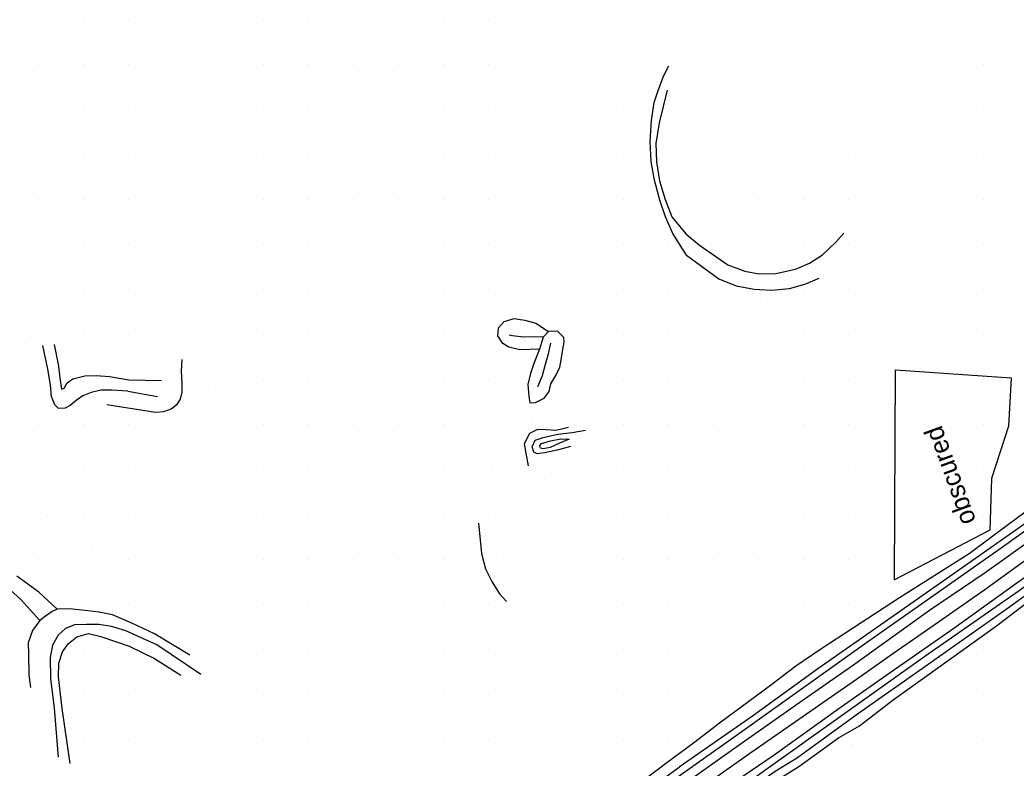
# Model space of a CAD drawing. Extents: x 524772 to 528246, y 273285 to 283088.
# Drawn here: x 526817.7 to 527033.7, y 277669.6 to 277831.8 of the extents above; entities that cross this region are included whole.
import ezdxf

# ---------------------------------------------------------------- set-up
doc = ezdxf.new("R2010")
doc.units = 0
for name, color, linetype in [('Exist DTM Crownline', 7, 'Continuous'), ('Exist Roads EOP', 7, 'Continuous'), ('Old_Level_12', 7, 'Continuous'), ('PH Exist DTM Breakline', 7, 'Continuous'), ('PH Exist DTM Point', 7, 'Continuous')]:
    doc.layers.add(name, color=color, linetype=linetype)

msp = doc.modelspace()

# ---------------------------------------------------------------- linework, layer by layer
at = {"layer": 'Exist DTM Crownline'}
msp.add_lwpolyline([(527093.29, 277754.92), (527081.03, 277746.29), (527067.8, 277736.57), (527053.6, 277726.78), (527037.66, 277716.04), (527026.92, 277708.27), (527016.11, 277700.77), (527006.93, 277694.41), (526999.08, 277688.78), (526989.17, 277681.93), (526976.35, 277673.09), (526967.09, 277666.46), (526959.31, 277660.84), (526949.06, 277653.53), (526940.89, 277647.53)], dxfattribs=at)
at = {"layer": 'Exist Roads EOP'}
for points in [[(526885.22, 277587.83), (526890.27, 277593.98), (526898.57, 277603.91), (526907.81, 277613.97), (526915.57, 277622.11), (526923.58, 277629.48), (526930.09, 277635.08), (526937.2, 277641.12), (526944.39, 277646.71), (526953.26, 277652.95), (526962.28, 277659.19), (526969.67, 277664.58), (526981.23, 277672.5), (526995.03, 277682.41), (527006.12, 277690.17), (527020.16, 277699.94), (527033.86, 277709.75), (527047.72, 277719.55), (527068.03, 277733.58), (527084.83, 277745.52), (527098.58, 277755.38)], [(527073.71, 277745.14), (527062.62, 277737.07), (527050.76, 277728.61), (527038.34, 277720.01), (527026.75, 277711.81), (527014.92, 277703.74), (526998.22, 277691.78), (526986.82, 277683.81), (526973.67, 277674.61), (526958.94, 277664.18), (526946.06, 277655.01), (526936.77, 277648.03), (526928.24, 277641.04), (526919.76, 277633.86), (526914.72, 277629.34), (526908.53, 277623.32), (526902.38, 277616.86), (526896.4, 277610.16), (526890.7, 277603.88), (526884.19, 277596.4), (526873.91, 277582.93)]]:
    msp.add_lwpolyline(points, dxfattribs=at)
at = {"layer": 'Old_Level_12'}
msp.add_lwpolyline([(527007.33, 277710.58), (527007.56, 277755.97), (527032.58, 277754.19), (527032.02, 277743.7), (527028.35, 277732.4), (527027.97, 277721.18), (527007.15, 277710.38)], dxfattribs=at)
at = {"layer": 'PH Exist DTM Breakline'}
for points in [[(526962.21, 277780.83), (526959.27, 277785.49), (526957.64, 277789.13), (526956.43, 277792.7), (526955.25, 277797.02), (526954.57, 277801.08), (526954.32, 277805.45), (526954.62, 277810.02), (526955.24, 277813.86), (526956.04, 277816.29), (526957.23, 277819.62), (526958.39, 277821.82)], [(526958, 277816.59), (526956.29, 277809.48), (526955.55, 277805.01), (526955.68, 277801), (526956.37, 277796.9), (526957.57, 277792.85), (526959.03, 277789.12), (526962.07, 277785.43), (526965.07, 277782.97)], [(526965.07, 277782.97), (526971.16, 277778.71), (526974.9, 277777.31), (526977.96, 277776.74), (526981.61, 277776.83), (526985.85, 277777.78), (526988.88, 277779.05), (526991.71, 277780.89), (526994.56, 277783.58), (526996.34, 277785.59)], [(526962.21, 277780.83), (526969.2, 277775.63), (526972.96, 277774.14), (526976.86, 277773.41), (526980.65, 277773.21), (526984.56, 277773.59), (526987.87, 277774.51), (526990.98, 277775.8)], [(526930.35, 277760.39), (526926.06, 277760.3), (526923.73, 277760.83), (526922.38, 277761.62), (526921.33, 277763.3), (526921.45, 277765.07), (526922.7, 277766.4), (526924.83, 277767.08), (526927.19, 277766.73), (526929.58, 277766.03), (526932.29, 277764.28)], [(526928.22, 277748.82), (526929.52, 277748.83), (526931.33, 277749.79), (526932.42, 277751.25), (526932.81, 277752.89), (526933.87, 277754.68), (526934.78, 277756.54), (526935.07, 277758.11), (526935.31, 277759.99), (526935.73, 277761.93), (526935.64, 277762.97), (526934.24, 277764.29), (526932.29, 277764.28), (526931.15, 277763.04), (526930.35, 277760.39), (526929.12, 277757.29), (526928.39, 277755.17), (526927.81, 277752.76), (526928.02, 277750.23), (526928.22, 277748.82)], [(526931.15, 277763.04), (526929.22, 277763.06), (526926.85, 277763.04), (526924.49, 277763.29), (526923.76, 277763.48)], [(526841.11, 277751.35), (526837.66, 277751.53), (526835.28, 277751.53), (526833.18, 277751.02), (526831.36, 277750.28), (526829.92, 277749.29), (526828.59, 277748.18), (526827.51, 277747.66), (526826.06, 277747.56), (526825.26, 277748.38), (526824.54, 277750.14), (526824.36, 277752.67), (526823.76, 277756.05), (526822.71, 277761.18)], [(526825.14, 277761.46), (526826.05, 277756.72), (526826.36, 277754.24), (526826.75, 277751.73), (526827.28, 277751.96), (526827.93, 277753.1), (526829.17, 277753.98), (526831.81, 277754.64), (526834.27, 277754.71), (526837.15, 277754.5), (526841.32, 277753.76)], [(526929.99, 277752.36), (526931.02, 277754.73), (526931.62, 277757.18), (526932.32, 277759.38), (526932.79, 277761.74)], [(526836.52, 277748.43), (526847.07, 277746.73), (526848.89, 277746.89), (526850.5, 277747.51), (526851.86, 277748.56), (526852.54, 277749.6), (526852.86, 277751.11), (526852.86, 277753), (526852.77, 277755.62), (526852.9, 277758.18)], [(526841.32, 277753.76), (526848.38, 277753.61)], [(527075.52, 277754.93), (527068.44, 277748.79), (527063.35, 277744.94), (527058.17, 277741.29), (527051.67, 277736.65), (527043.67, 277731.01), (527032.04, 277722.43), (527023.53, 277716.09), (527008.38, 277706.51), (526998.17, 277699.85), (526991.36, 277695.39), (526985.93, 277691.7), (526980.41, 277687.52), (526969.4, 277679.37), (526963.99, 277675.24), (526957.69, 277670.53)], [(527079.57, 277754.11), (527075.01, 277750.71), (527070.26, 277747.22), (527065.63, 277743.82), (527060.79, 277740.44), (527056.56, 277737.99), (527053.73, 277735.59), (527045.46, 277729.87), (527038.27, 277724.47), (527022.21, 277713.17), (527003.65, 277700.19), (526990.72, 277691.1), (526976.52, 277680.84), (526960.65, 277669.83)], [(526841.11, 277751.35), (526847.57, 277750.16)], [(526942.58, 277655.06), (526958.38, 277666.35), (526976, 277678.83), (527000.52, 277696.3), (527030.41, 277717.38), (527054.44, 277734.53), (527067, 277743.33), (527080.48, 277752.77)], [(526936.64, 277743.43), (526933.9, 277742.8), (526931.82, 277742.93), (526929.93, 277743.04), (526928.15, 277742.12), (526927.03, 277739.93), (526927.36, 277737.87), (526927.93, 277735.13)], [(526937.04, 277739.33), (526934.45, 277738.57), (526931.41, 277737.95), (526929.86, 277737.71), (526929.14, 277738.11), (526928.76, 277739.26), (526929.41, 277740.69), (526931.17, 277741.26), (526934.33, 277741.97), (526937.45, 277742.37), (526940.29, 277742.84)], [(526936.78, 277740.9), (526934.71, 277740.04), (526932.67, 277739.14), (526931.13, 277738.8), (526930.6, 277738.98), (526930.46, 277739.51), (526930.79, 277739.98), (526932.76, 277740.58), (526934.99, 277740.98), (526936.78, 277740.9)], [(527058.86, 277725.19), (527048.05, 277718.02), (527034.11, 277707.88), (527013.87, 277693.78), (526988.75, 277675.91), (526966.56, 277660.08)], [(526917.15, 277722.71), (526917.75, 277716.1), (526918.62, 277712.82), (526920.05, 277710.08), (526921.68, 277707.36), (526923.17, 277705.69)], [(526967.43, 277659.07), (526981.45, 277668.96), (526986.25, 277671.89), (526999.31, 277681.36), (527011.45, 277689.89), (527031.49, 277704.04), (527043.48, 277712.72), (527057.63, 277722.76)], [(526968.48, 277657.57), (526979.98, 277665.83), (526986.56, 277669.97), (526995.15, 277676.16), (526999.73, 277678.75), (527007.02, 277684.39), (527029.45, 277700.46), (527036.17, 277705.56), (527043.04, 277710.22), (527053.9, 277717.96)], [(526798.27, 277713.39), (526807.25, 277712.33), (526812.14, 277710.59), (526815.66, 277708.2), (526817.9, 277706.15), (526822.02, 277701.62)], [(526825.79, 277704.08), (526821.82, 277707.78), (526817.02, 277711.2)], [(526854.54, 277694.09), (526846.9, 277698.75), (526842, 277701.01), (526837.78, 277702.82), (526834.86, 277703.38), (526832.45, 277703.7), (526828.44, 277704.1), (526825.79, 277704.08), (526824.72, 277703.58), (526823.23, 277702.57), (526822.02, 277701.62), (526820.46, 277699.43), (526819.5, 277696.77), (526819.58, 277694.27), (526819.66, 277689.81), (526820, 277687.1)], [(526856.96, 277689.91), (526847.41, 277696.3), (526840.69, 277699.38), (526837.6, 277700.32), (526834.87, 277700.74), (526832.16, 277700.76), (526829.53, 277700.67), (526827.56, 277699.9), (526825.98, 277698.39), (526824.76, 277696.28), (526824.25, 277693.56), (526824.34, 277689.02), (526825.15, 277682.57), (526826.04, 277671.99)], [(526828.63, 277670.63), (526826.89, 277682.54), (526826.06, 277689.36), (526826.17, 277692.35), (526826.98, 277694.78), (526828.22, 277696.62), (526830.07, 277698.08), (526832.56, 277698.79), (526835.24, 277698.13), (526841.43, 277696.02), (526846.87, 277693.35), (526852.59, 277689.72)], [(526957.69, 277670.53), (526948.03, 277663.24), (526943.52, 277659.92), (526939.57, 277656.8), (526936.9, 277654.7), (526934.42, 277652.53), (526930.44, 277649.43), (526926.91, 277646.85), (526922.77, 277643.7), (526917.51, 277639.25), (526915.3, 277637.35), (526912.49, 277634.7), (526910.31, 277632.45), (526908.73, 277631.24), (526907.63, 277630.54), (526906.22, 277630.82), (526904.48, 277631.8), (526902.72, 277633.12), (526900.72, 277635.16), (526897.24, 277638.62)], [(526906.73, 277627.75), (526910.97, 277630.83), (526917.85, 277636.34), (526926.38, 277643.64), (526931.93, 277648.51), (526935.95, 277651.72), (526940.95, 277655.65), (526944.84, 277658.6), (526948.95, 277661.37), (526955.16, 277665.84), (526960.65, 277669.83)]]:
    msp.add_lwpolyline(points, dxfattribs=at)
at = {"layer": 'PH Exist DTM Point'}
for p, q in [((526821.81, 277831.79), (526821.81, 277831.79)), ((526831.56, 277831.79), (526831.56, 277831.79)), ((526841.32, 277831.79), (526841.32, 277831.79)), ((526851.07, 277831.79), (526851.07, 277831.79)), ((526860.82, 277831.79), (526860.82, 277831.79)), ((526870.58, 277831.79), (526870.58, 277831.79)), ((526880.33, 277831.79), (526880.33, 277831.79)), ((526890.09, 277831.79), (526890.09, 277831.79)), ((526899.84, 277831.79), (526899.84, 277831.79)), ((526909.59, 277831.79), (526909.59, 277831.79)), ((526919.35, 277831.79), (526919.35, 277831.79)), ((526929.1, 277831.79), (526929.1, 277831.79)), ((526938.85, 277831.79), (526938.85, 277831.79)), ((526821.81, 277822.03), (526821.81, 277822.03)), ((526831.56, 277822.03), (526831.56, 277822.03)), ((526841.32, 277822.03), (526841.32, 277822.03)), ((526851.07, 277822.03), (526851.07, 277822.03)), ((526860.82, 277822.03), (526860.82, 277822.03)), ((526870.58, 277822.03), (526870.58, 277822.03)), ((526880.33, 277822.03), (526880.33, 277822.03)), ((526890.09, 277822.03), (526890.09, 277822.03)), ((526899.84, 277822.03), (526899.84, 277822.03)), ((526909.57, 277822.05), (526909.57, 277822.05)), ((526919.35, 277822.03), (526919.35, 277822.03)), ((526929.1, 277822.03), (526929.1, 277822.03)), ((526938.85, 277822.03), (526938.85, 277822.03)), ((527026.64, 277822.03), (527026.64, 277822.03)), ((526821.81, 277812.28), (526821.81, 277812.28)), ((526831.56, 277812.28), (526831.56, 277812.28)), ((526841.32, 277812.28), (526841.32, 277812.28)), ((526851.07, 277812.28), (526851.07, 277812.28)), ((526860.82, 277812.28), (526860.82, 277812.28)), ((526870.58, 277812.28), (526870.58, 277812.28)), ((526880.33, 277812.28), (526880.33, 277812.28)), ((526890.09, 277812.28), (526890.09, 277812.28)), ((526899.84, 277812.28), (526899.84, 277812.28)), ((526909.59, 277812.28), (526909.59, 277812.28)), ((526919.35, 277812.28), (526919.35, 277812.28)), ((526929.1, 277812.28), (526929.1, 277812.28)), ((526938.85, 277812.28), (526938.85, 277812.28)), ((526948.58, 277812.29), (526948.58, 277812.29)), ((527007.13, 277812.28), (527007.13, 277812.28)), ((527016.88, 277812.28), (527016.88, 277812.28)), ((527026.64, 277812.28), (527026.64, 277812.28)), ((526821.81, 277802.53), (526821.81, 277802.53)), ((526831.56, 277802.53), (526831.56, 277802.53)), ((526841.32, 277802.53), (526841.32, 277802.53)), ((526851.07, 277802.53), (526851.07, 277802.53)), ((526860.82, 277802.53), (526860.82, 277802.53)), ((526870.58, 277802.53), (526870.58, 277802.53)), ((526880.33, 277802.53), (526880.33, 277802.53)), ((526890.09, 277802.53), (526890.09, 277802.53)), ((526899.84, 277802.53), (526899.84, 277802.53)), ((526909.59, 277802.53), (526909.59, 277802.53)), ((526919.32, 277802.54), (526919.32, 277802.54)), ((526929.12, 277802.51), (526929.12, 277802.51)), ((526938.83, 277802.54), (526938.83, 277802.54)), ((526948.58, 277802.54), (526948.58, 277802.54)), ((526997.38, 277802.53), (526997.38, 277802.53)), ((527007.13, 277802.53), (527007.13, 277802.53)), ((527016.88, 277802.53), (527016.88, 277802.53)), ((527026.64, 277802.53), (527026.64, 277802.53)), ((526821.81, 277792.77), (526821.81, 277792.77)), ((526831.56, 277792.77), (526831.56, 277792.77)), ((526841.32, 277792.77), (526841.32, 277792.77)), ((526851.07, 277792.77), (526851.07, 277792.77)), ((526860.82, 277792.77), (526860.82, 277792.77)), ((526870.58, 277792.77), (526870.58, 277792.77)), ((526880.33, 277792.77), (526880.33, 277792.77)), ((526890.09, 277792.77), (526890.09, 277792.77)), ((526899.84, 277792.77), (526899.84, 277792.77)), ((526909.59, 277792.77), (526909.59, 277792.77)), ((526919.37, 277792.76), (526919.37, 277792.76)), ((526929.08, 277792.78), (526929.08, 277792.78)), ((526938.88, 277792.76), (526938.88, 277792.76)), ((526948.61, 277792.77), (526948.61, 277792.77)), ((526977.87, 277792.77), (526977.87, 277792.77)), ((526987.62, 277792.77), (526987.62, 277792.77)), ((526997.38, 277792.77), (526997.38, 277792.77)), ((527007.13, 277792.77), (527007.13, 277792.77)), ((527016.88, 277792.77), (527016.88, 277792.77)), ((527026.64, 277792.77), (527026.64, 277792.77)), ((526821.81, 277783.02), (526821.81, 277783.02)), ((526831.56, 277783.02), (526831.56, 277783.02)), ((526841.32, 277783.02), (526841.32, 277783.02)), ((526851.07, 277783.02), (526851.07, 277783.02)), ((526860.84, 277783.02), (526860.84, 277783.02)), ((526870.58, 277783.02), (526870.58, 277783.02)), ((526880.33, 277783.02), (526880.33, 277783.02)), ((526890.09, 277783.02), (526890.09, 277783.02)), ((526899.84, 277783.02), (526899.84, 277783.02)), ((526909.59, 277783.02), (526909.59, 277783.02)), ((526919.35, 277783.02), (526919.35, 277783.02)), ((526929.1, 277783.02), (526929.1, 277783.02)), ((526938.85, 277783.02), (526938.85, 277783.02)), ((526948.61, 277783.02), (526948.61, 277783.02)), ((526958.36, 277783.02), (526958.36, 277783.02)), ((526968.11, 277783.02), (526968.11, 277783.02)), ((526977.87, 277783.02), (526977.87, 277783.02)), ((526987.62, 277783.02), (526987.62, 277783.02)), ((526997.38, 277783.02), (526997.38, 277783.02)), ((527007.13, 277783.02), (527007.13, 277783.02)), ((527016.88, 277783.02), (527016.88, 277783.02)), ((527026.64, 277783.02), (527026.64, 277783.02)), ((526821.81, 277773.26), (526821.81, 277773.26)), ((526831.56, 277773.26), (526831.56, 277773.26)), ((526841.32, 277773.26), (526841.32, 277773.26)), ((526851.07, 277773.26), (526851.07, 277773.26)), ((526860.82, 277773.26), (526860.82, 277773.26)), ((526870.58, 277773.26), (526870.58, 277773.26)), ((526880.33, 277773.26), (526880.33, 277773.26)), ((526890.11, 277773.25), (526890.11, 277773.25)), ((526899.84, 277773.26), (526899.84, 277773.26)), ((526909.59, 277773.26), (526909.59, 277773.26)), ((526919.35, 277773.26), (526919.35, 277773.26)), ((526929.1, 277773.26), (526929.1, 277773.26)), ((526938.85, 277773.26), (526938.85, 277773.26)), ((526948.61, 277773.26), (526948.61, 277773.26)), ((526958.36, 277773.26), (526958.36, 277773.26)), ((526968.11, 277773.26), (526968.11, 277773.26)), ((526987.62, 277773.26), (526987.62, 277773.26)), ((526997.38, 277773.26), (526997.38, 277773.26)), ((527007.13, 277773.26), (527007.13, 277773.26)), ((527016.88, 277773.26), (527016.88, 277773.26)), ((527026.64, 277773.26), (527026.64, 277773.26)), ((526978.16, 277771.32), (526978.16, 277771.32)), ((526831.56, 277763.51), (526831.56, 277763.51)), ((526841.32, 277763.51), (526841.32, 277763.51)), ((526851.07, 277763.51), (526851.07, 277763.51)), ((526860.82, 277763.51), (526860.82, 277763.51)), ((526870.58, 277763.51), (526870.58, 277763.51)), ((526880.33, 277763.51), (526880.33, 277763.51)), ((526890.06, 277763.52), (526890.06, 277763.52)), ((526899.84, 277763.51), (526899.84, 277763.51)), ((526909.59, 277763.51), (526909.59, 277763.51)), ((526940.48, 277762.25), (526940.48, 277762.25)), ((526948.61, 277763.51), (526948.61, 277763.51)), ((526958.36, 277763.51), (526958.36, 277763.51)), ((526968.11, 277763.51), (526968.11, 277763.51)), ((526977.87, 277763.51), (526977.87, 277763.51)), ((526987.62, 277763.51), (526987.62, 277763.51)), ((526997.38, 277763.51), (526997.38, 277763.51)), ((527007.13, 277763.51), (527007.13, 277763.51)), ((527016.88, 277763.51), (527016.88, 277763.51)), ((527026.64, 277763.51), (527026.64, 277763.51)), ((526818.94, 277761.75), (526818.94, 277761.75)), ((526832.93, 277759.04), (526832.93, 277759.04)), ((526821.62, 277753.7), (526821.62, 277753.7)), ((526841.32, 277753.76), (526841.32, 277753.76)), ((526851.09, 277753.76), (526851.09, 277753.76)), ((526870.58, 277753.76), (526870.58, 277753.76)), ((526880.33, 277753.76), (526880.33, 277753.76)), ((526890.09, 277753.76), (526890.09, 277753.76)), ((526899.84, 277753.76), (526899.84, 277753.76)), ((526909.59, 277753.76), (526909.59, 277753.76)), ((526919.35, 277753.76), (526919.35, 277753.76)), ((526938.85, 277753.76), (526938.85, 277753.76)), ((526948.61, 277753.76), (526948.61, 277753.76)), ((526958.36, 277753.76), (526958.36, 277753.76)), ((526968.11, 277753.76), (526968.11, 277753.76)), ((526977.87, 277753.76), (526977.87, 277753.76)), ((526987.62, 277753.76), (526987.62, 277753.76)), ((526997.38, 277753.76), (526997.38, 277753.76)), ((527007.13, 277753.76), (527007.13, 277753.76)), ((527016.88, 277753.76), (527016.88, 277753.76)), ((527026.64, 277753.76), (527026.64, 277753.76)), ((526858.56, 277752.25), (526858.56, 277752.25)), ((526928.65, 277745.29), (526928.65, 277745.29)), ((526941.17, 277746.09), (526941.17, 277746.09)), ((526976.67, 277744.95), (526976.67, 277744.95)), ((526821.79, 277744), (526821.79, 277744)), ((526831.54, 277744.02), (526831.54, 277744.02)), ((526841.32, 277744), (526841.32, 277744)), ((526851.05, 277744), (526851.05, 277744)), ((526860.82, 277744), (526860.82, 277744)), ((526870.58, 277744), (526870.58, 277744)), ((526880.33, 277744), (526880.33, 277744)), ((526890.09, 277744), (526890.09, 277744)), ((526899.84, 277744), (526899.84, 277744)), ((526909.56, 277744.01), (526909.56, 277744.01)), ((526920.68, 277743.15), (526920.68, 277743.15)), ((526948.61, 277744), (526948.61, 277744)), ((526958.36, 277744), (526958.36, 277744)), ((526968.11, 277744), (526968.11, 277744)), ((526987.62, 277744), (526987.62, 277744)), ((526997.38, 277744), (526997.38, 277744)), ((527007.13, 277744), (527007.13, 277744)), ((527016.88, 277744), (527016.88, 277744)), ((527026.64, 277744), (527026.64, 277744)), ((526824.12, 277734.27), (526824.12, 277734.27)), ((526831.56, 277734.25), (526831.56, 277734.25)), ((526841.32, 277734.25), (526841.32, 277734.25)), ((526851.07, 277734.25), (526851.07, 277734.25)), ((526860.82, 277734.25), (526860.82, 277734.25)), ((526870.58, 277734.25), (526870.58, 277734.25)), ((526880.33, 277734.25), (526880.33, 277734.25)), ((526890.07, 277734.24), (526890.07, 277734.24)), ((526899.84, 277734.25), (526899.84, 277734.25)), ((526909.62, 277734.25), (526909.62, 277734.25)), ((526920.02, 277734.08), (526920.02, 277734.08)), ((526938.84, 277734.27), (526938.84, 277734.27)), ((526948.61, 277734.25), (526948.61, 277734.25)), ((526958.36, 277734.25), (526958.36, 277734.25)), ((526968.11, 277734.25), (526968.11, 277734.25)), ((526977.87, 277734.25), (526977.87, 277734.25)), ((526987.62, 277734.25), (526987.62, 277734.25)), ((526997.38, 277734.25), (526997.38, 277734.25)), ((527007.13, 277734.25), (527007.13, 277734.25)), ((527016.88, 277734.25), (527016.88, 277734.25)), ((527026.64, 277734.25), (527026.64, 277734.25)), ((526931.48, 277732.48), (526931.48, 277732.48)), ((526823.61, 277724.45), (526823.61, 277724.45)), ((526831.56, 277724.5), (526831.56, 277724.5)), ((526841.32, 277724.5), (526841.32, 277724.5)), ((526851.07, 277724.5), (526851.07, 277724.5)), ((526860.82, 277724.5), (526860.82, 277724.5)), ((526870.58, 277724.5), (526870.58, 277724.5)), ((526880.33, 277724.5), (526880.33, 277724.5)), ((526890.09, 277724.5), (526890.09, 277724.5)), ((526899.84, 277724.5), (526899.84, 277724.5)), ((526909.59, 277724.5), (526909.59, 277724.5)), ((526919.35, 277724.5), (526919.35, 277724.5)), ((526929.1, 277724.5), (526929.1, 277724.5)), ((526938.85, 277724.5), (526938.85, 277724.5)), ((526948.61, 277724.5), (526948.61, 277724.5)), ((526958.36, 277724.5), (526958.36, 277724.5)), ((526968.11, 277724.5), (526968.11, 277724.5)), ((526977.87, 277724.5), (526977.87, 277724.5)), ((526987.62, 277724.5), (526987.62, 277724.5)), ((526997.38, 277724.5), (526997.38, 277724.5)), ((527007.13, 277724.5), (527007.13, 277724.5)), ((527016.88, 277724.5), (527016.88, 277724.5)), ((527026.63, 277724.47), (527026.63, 277724.47)), ((526833.25, 277717.33), (526833.25, 277717.33)), ((526821.81, 277714.74), (526821.81, 277714.74)), ((526841.32, 277714.74), (526841.32, 277714.74)), ((526851.07, 277714.74), (526851.07, 277714.74)), ((526860.81, 277714.73), (526860.81, 277714.73)), ((526870.58, 277714.74), (526870.58, 277714.74)), ((526880.35, 277714.75), (526880.35, 277714.75)), ((526890.1, 277714.75), (526890.1, 277714.75)), ((526899.84, 277714.74), (526899.84, 277714.74)), ((526909.59, 277714.74), (526909.59, 277714.74)), ((526921.08, 277715.26), (526921.08, 277715.26)), ((526929.1, 277714.74), (526929.1, 277714.74)), ((526938.85, 277714.74), (526938.85, 277714.74)), ((526948.61, 277714.74), (526948.61, 277714.74)), ((526958.36, 277714.74), (526958.36, 277714.74)), ((526968.11, 277714.74), (526968.11, 277714.74)), ((526977.87, 277714.74), (526977.87, 277714.74)), ((526987.62, 277714.74), (526987.62, 277714.74)), ((526997.38, 277714.74), (526997.38, 277714.74)), ((527007.13, 277714.74), (527007.13, 277714.74)), ((527016.89, 277714.77), (527016.89, 277714.77)), ((526841.32, 277704.99), (526841.32, 277704.99)), ((526851.07, 277704.99), (526851.07, 277704.99)), ((526860.84, 277705), (526860.84, 277705)), ((526870.58, 277704.99), (526870.58, 277704.99)), ((526880.33, 277704.99), (526880.33, 277704.99)), ((526890.07, 277704.98), (526890.07, 277704.98)), ((526899.84, 277704.99), (526899.84, 277704.99)), ((526909.59, 277704.99), (526909.59, 277704.99)), ((526919.35, 277704.99), (526919.35, 277704.99)), ((526929.1, 277704.99), (526929.1, 277704.99)), ((526938.84, 277705), (526938.84, 277705)), ((526948.61, 277704.99), (526948.61, 277704.99)), ((526958.36, 277704.99), (526958.36, 277704.99)), ((526968.11, 277704.99), (526968.11, 277704.99)), ((526977.87, 277704.99), (526977.87, 277704.99)), ((526987.62, 277704.99), (526987.62, 277704.99)), ((526997.38, 277704.99), (526997.38, 277704.99)), ((526860.77, 277700.18), (526860.77, 277700.18)), ((526854.37, 277697.4), (526854.37, 277697.4)), ((526821.81, 277695.24), (526821.81, 277695.24)), ((526831.56, 277695.24), (526831.56, 277695.24)), ((526870.58, 277695.24), (526870.58, 277695.24)), ((526880.33, 277695.24), (526880.33, 277695.24)), ((526890.09, 277695.24), (526890.09, 277695.24)), ((526899.84, 277695.24), (526899.84, 277695.24)), ((526909.59, 277695.24), (526909.59, 277695.24)), ((526919.35, 277695.24), (526919.35, 277695.24)), ((526929.1, 277695.24), (526929.1, 277695.24)), ((526938.85, 277695.24), (526938.85, 277695.24)), ((526948.61, 277695.24), (526948.61, 277695.24)), ((526958.36, 277695.24), (526958.36, 277695.24)), ((526968.11, 277695.24), (526968.11, 277695.24)), ((526977.87, 277695.24), (526977.87, 277695.24)), ((526987.62, 277695.24), (526987.62, 277695.24)), ((527026.64, 277695.24), (527026.64, 277695.24)), ((526821.81, 277685.48), (526821.81, 277685.48)), ((526831.56, 277685.48), (526831.56, 277685.48)), ((526841.32, 277685.48), (526841.32, 277685.48)), ((526851.07, 277685.48), (526851.07, 277685.48)), ((526860.85, 277685.48), (526860.85, 277685.48)), ((526870.58, 277685.48), (526870.58, 277685.48)), ((526880.33, 277685.48), (526880.33, 277685.48)), ((526890.09, 277685.48), (526890.09, 277685.48)), ((526899.84, 277685.48), (526899.84, 277685.48)), ((526909.59, 277685.48), (526909.59, 277685.48)), ((526919.35, 277685.48), (526919.35, 277685.48)), ((526929.1, 277685.48), (526929.1, 277685.48)), ((526938.85, 277685.48), (526938.85, 277685.48)), ((526948.61, 277685.48), (526948.61, 277685.48)), ((526958.36, 277685.48), (526958.36, 277685.48)), ((526968.11, 277685.48), (526968.11, 277685.48)), ((527016.88, 277685.48), (527016.88, 277685.48)), ((527026.64, 277685.48), (527026.64, 277685.48)), ((526821.81, 277675.73), (526821.81, 277675.73)), ((526831.56, 277675.73), (526831.56, 277675.73)), ((526841.32, 277675.73), (526841.32, 277675.73)), ((526851.07, 277675.73), (526851.07, 277675.73)), ((526870.58, 277675.73), (526870.58, 277675.73)), ((526880.33, 277675.73), (526880.33, 277675.73)), ((526890.09, 277675.73), (526890.09, 277675.73)), ((526899.84, 277675.73), (526899.84, 277675.73)), ((526909.59, 277675.73), (526909.59, 277675.73)), ((526919.35, 277675.73), (526919.35, 277675.73)), ((526929.1, 277675.73), (526929.1, 277675.73)), ((526938.85, 277675.73), (526938.85, 277675.73)), ((526948.61, 277675.73), (526948.61, 277675.73)), ((526958.36, 277675.73), (526958.36, 277675.73)), ((527007.13, 277675.73), (527007.13, 277675.73)), ((527016.88, 277675.73), (527016.88, 277675.73)), ((527026.64, 277675.73), (527026.64, 277675.73)), ((526863.99, 277675.4), (526863.99, 277675.4)), ((526997.92, 277674.76), (526997.92, 277674.76))]:
    msp.add_line(p, q, dxfattribs=at)

# ---------------------------------------------------------------- texts
at = {"layer": 'Old_Level_12'}
msp.add_text('obscured', height=4.05, rotation=110, dxfattribs=at).set_placement((527025.05, 277723.19))

doc.saveas('drawing.dxf')
